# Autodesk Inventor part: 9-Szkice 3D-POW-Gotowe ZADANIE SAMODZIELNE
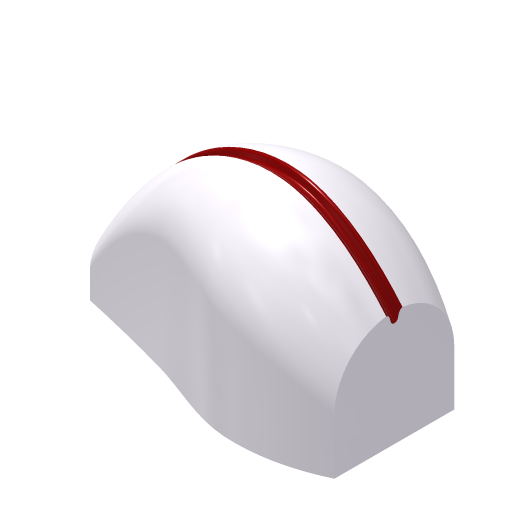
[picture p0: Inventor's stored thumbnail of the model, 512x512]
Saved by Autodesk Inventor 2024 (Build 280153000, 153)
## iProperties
Company: ATC
Created: 2023-03
Part Number: 9-Szkice 3D-POW-Gotowe ZADANIE SAMODZIELNE
Document SubType Name: Modeling
Designer: Andrzej Jaskulski
Density: 1 g/cm^3
Material: Kurs-AJ
Appearance: Kurs-AJ
Checked By: A.J.
Engr Approved By: Andrzej Jaskulski
Mfg Approved By: Andrzej Jaskulski
Authority: A.J.
Title: A.J.: Kurs R2024-MEP
Author: Andrzej Jaskulski
Revision Number: 1/24
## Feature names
1. BAZA
2. ROWEK
## Parameters: d3 = 0, d4 = 90 deg, d5 = 0, d6 = 90 deg, d7 = 0, d8 = 90 deg, d9 = 0, d10 = 90 deg, d11 = 13 mm, d12 = 6 mm, d13 = 17 mm, d14 = 11 mm, d15 = 11 mm, d16 = 12 mm, d17 = 6 mm, d18 = 3 mm, d22 = 0.5 mm, d23 = 0.4 mm, d24 = 0.7 mm, d25 = 0.3 mm, d26 = 2 mm, d27 = 6.45 mm, d32 = 0, d34 = 15 deg, d35 = 15 deg, d36 = 0
